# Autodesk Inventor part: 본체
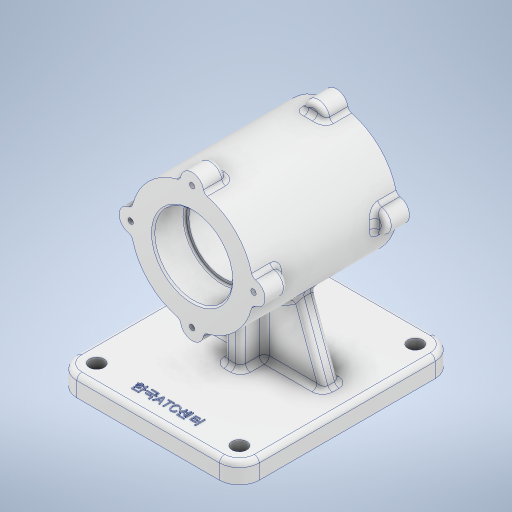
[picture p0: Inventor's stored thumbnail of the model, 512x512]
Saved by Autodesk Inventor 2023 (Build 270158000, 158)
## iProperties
Created: 2023-08
Part Number: 본체
Material: 알루미늄 6061
Document SubType Name: Modeling
Designer: asung
Density: 2.7 g/cm^3
Appearance: 알루미늄 - 평지
Author: asung
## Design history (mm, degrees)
sketch "스케치1"
  geometry: L1 (43, 65)-(-43, 65); L2 (-55, 53)-(-55, -53); L3 (-43, -65)-(43, -65); L4 (55, -53)-(55, 53); L5 (55, 65)-(-55, -65); L6 (-55, 65)-(55, -65); C1 r 4.5 at (-43, 53); C2 r 4.5 at (43, 53); C3 r 4.5 at (43, -53); C4 r 4.5 at (-43, -53); A1 r 12 centre (43, 53) between (55, 53) and (43, 65); A2 r 12 centre (-43, 53) between (-43, 65) and (-55, 53); A3 r 12 centre (-43, -53) between (-55, -53) and (-43, -65); A4 r 12 centre (43, -53) between (43, -65) and (55, -53); 1 further point
  constraints: 12 end point, 8 centre point, 8 point on circle, 8 point on line, 8 tangent, 4 coincident, 3 equal radius, 2 midpoint, 2 parallel, 1 horizontal, 1 perpendicular
  dimensions: "d0" = 110 distance of L6.end L5.end; "d1" = 130 distance of L5.end L6.start; "d2" = 12 radius of A1; "d3" = 9 diameter of C1; "d4" = 9 diameter of C2; "d5" = 9 diameter of C3; "d6" = 9 diameter of C4
extrude "돌출1" new body sketch "스케치1" distance "d7" = 12; taper "d8" = 0 deg
fillet "모깎기1" dims "d9" = 3
node "작업 평면1"
sketch "스케치2"
  geometry: L1 (-9, 12)-(115, 12) reference; L2 (118, 9)-(118, 0) reference; L3 (118, 0)-(-12, 0) reference; L4 (-12, 0)-(-12, 9) reference; A1 r 3 centre (-9, 9) between (-9, 12) and (-12, 9) reference; A2 r 3 centre (115, 9) between (118, 9) and (115, 12) reference; 1 further point
  node "절단 모서리 투영1"
sketch "스케치3"
  geometry: L1 (-9, 12)-(115, 12) reference; L2 (118, 9)-(118, 0) reference; L3 (118, 0)-(-12, 0) reference; L4 (-12, 0)-(-12, 9) reference; L5 (58, 0)-(58, 82); L6 (-12, 0)-(58, 0); L7 (14.5, 82)-(101.5, 82); L8 (101.5, 82)-(101.5, 119); L9 (101.5, 119)-(14.5, 119); L10 (14.5, 119)-(14.5, 82); A1 r 3 centre (-9, 9) between (-9, 12) and (-12, 9) reference; A2 r 3 centre (115, 9) between (118, 9) and (115, 12) reference; 1 further point
  constraints: 12 end point, 2 vertical, 1 horizontal, 1 midpoint, 1 perpendicular, 1 point on line
  dimensions: "d10" = 82 distance of L5.start L5.end; "d11" = 70 distance of L3.end L5.start; "d12" = 87 distance of L7.start L7.end; "d13" = 37 distance of L7.end L8.end; "d14" = 87 distance of L8.end L9.end
revolve "회전1" sketch "스케치3" stored, may be unused: angle "d15" = 90 deg
sketch "스케치4"
  geometry: C1 r 37 at (0, 0) reference; 2 further points
  constraints: 1 coincident
hole "구멍1" sketch "스케치4" at (0, 0) diameter "d16" = 42; stored, may be unused: countersink angle "d20" = 90 deg, drill point angle "d22" = 0 deg; dims "d17" = 10, "d18" = 47, "d19" = 19, "d21" = 45
sketch "스케치5"
  geometry: C1 r 37 at (0, 0) reference; 2 further points
  constraints: 1 coincident
hole "구멍2" sketch "스케치5" at (0, 0) diameter "d23" = 42; stored, may be unused: countersink angle "d27" = 90 deg, drill point angle "d29" = 0 deg; dims "d24" = 6, "d25" = 47, "d26" = 19, "d28" = 45
fillet "모깎기2" dims "d30" = 1
chamfer "모따기1" distance "d31" = 1; stored, may be unused: second distance "d32" = 2, angle "d33" = 45 deg
sketch "스케치6"
  geometry: C1 r 24.5 at (0, 0) reference; C2 r 7 at (0, 37); 2 further points
  constraints: 1 centre point, 1 vertical alignment, 1 other
  dimensions: "d34" = 14 diameter of C2
extrude "돌출2" join sketch "스케치6" distance "d35" = 14; taper "d36" = 0 deg
sketch "스케치7"
  geometry: 1 further point
sketch "스케치8"
  geometry: A1 r 7 centre (0, 0) between (6.969, -0.662) and (-6.969, -0.662) reference; 2 further points
  constraints: 1 coincident
hole "구멍3" sketch "스케치8" at (0, 0) diameter "d37" = 3.242; stored, may be unused: countersink angle "d41" = 90 deg, drill point angle "d43" = 118 deg; dims "d38" = 8, "d39" = 47, "d40" = 19, "d42" = 10
fillet "모깎기3" dims "d44" = 3
fillet "모깎기4" dims "d45" = 3
node "작업 평면2"
sketch "스케치9"
  geometry: L1 (0, -62)-(0, 62) reference; L2 (-43, -65)-(43, -65) reference; L3 (-55, 53)-(-55, -53) reference; L4 (43, 65)-(-43, 65) reference; L5 (55, -53)-(55, 53) reference; C1 r 4.5 at (43, 53) reference; C2 r 4.5 at (-43, 53) reference; C3 r 4.5 at (-43, -53) reference; C4 r 4.5 at (43, -53) reference; A1 r 12 centre (43, -53) between (43, -65) and (55, -53) reference; A2 r 12 centre (-43, -53) between (-55, -53) and (-43, -65) reference; A3 r 12 centre (-43, 53) between (-43, 65) and (-55, 53) reference; A4 r 12 centre (43, 53) between (55, 53) and (43, 65) reference; 2 further points
  constraints: 1 other
  dimensions: "d49" = 0 distance from line of L1 point (0, -53); "d50" = 0 vertical distance of C3.centre point (0, -53)
feature "엠보싱1" sketch "스케치9" dims "d0" = 110, "d1" = 130, "d2" = 12, "d3" = 9, "d4" = 9, "d5" = 9, "d6" = 9, "d51" = 0.5, "d52" = 0
sketch "스케치10"
  geometry: L1 (1.971, 12)-(1.971, 12.5) reference; L2 (1.971, 12.5)-(2.385, 12.5) reference; L3 (2.385, 12.5)-(2.385, 12) reference; L4 (2.385, 12)-(115, 12) reference; L5 (118, 9)-(118, 0) reference; L6 (118, 0)-(-12, 0) reference; L7 (-12, 0)-(-12, 9) reference; L8 (-9, 12)-(1.971, 12) reference; L9 (14.5, 57.5)-(15.5, 58.5) reference; L10 (15.5, 58.5)-(32.5, 58.5) reference; L11 (33.5, 59.5)-(33.5, 61) reference; L12 (33.5, 61)-(82.5, 61) reference; L13 (82.5, 61)-(82.5, 59.5) reference; L14 (83.5, 58.5)-(100.5, 58.5) reference; L15 (100.5, 58.5)-(101.5, 57.5) reference; L16 (101.5, 57.5)-(101.5, 46.621) reference; L17 (101.5, 46.621)-(91.5, 46.621) reference; L18 (91.5, 46.621)-(90.526, 45) reference; L19 (90.526, 45)-(91.5, 43.379) reference; L20 (91.5, 43.379)-(101.5, 43.379) reference; L21 (101.5, 43.379)-(101.5, 38) reference; L22 (101.5, 38)-(90.5, 38) reference; L23 (87.5, 41)-(87.5, 42) reference; L24 (84.5, 45)-(31.5, 45) reference; L25 (28.5, 42)-(28.5, 41) reference; L26 (25.5, 38)-(14.5, 38) reference; L27 (14.5, 38)-(14.5, 43.379) reference; L28 (14.5, 43.379)-(24.5, 43.379) reference; L29 (24.5, 43.379)-(25.474, 45) reference; L30 (25.474, 45)-(24.5, 46.621) reference; L31 (24.5, 46.621)-(14.5, 46.621) reference; L32 (14.5, 46.621)-(14.5, 57.5) reference; L33 (15.5, 105.5)-(14.5, 106.5) reference; L34 (14.5, 106.5)-(14.5, 117.379) reference; L35 (14.5, 117.379)-(24.5, 117.379) reference; L36 (24.5, 117.379)-(25.474, 119) reference; L37 (25.474, 119)-(24.5, 120.621) reference; L38 (24.5, 120.621)-(14.5, 120.621) reference; L39 (14.5, 120.621)-(14.5, 126) reference; L40 (14.5, 126)-(25.5, 126) reference; L41 (28.5, 123)-(28.5, 122) reference; L42 (31.5, 119)-(84.5, 119) reference; L43 (87.5, 122)-(87.5, 123) reference; L44 (90.5, 126)-(101.5, 126) reference; L45 (101.5, 126)-(101.5, 120.621) reference; L46 (101.5, 120.621)-(91.5, 120.621) reference; L47 (91.5, 120.621)-(90.526, 119) reference; L48 (90.526, 119)-(91.5, 117.379) reference; L49 (91.5, 117.379)-(101.5, 117.379) reference; L50 (101.5, 117.379)-(101.5, 106.5) reference; L51 (101.5, 106.5)-(100.5, 105.5) reference; L52 (100.5, 105.5)-(83.5, 105.5) reference; L53 (82.5, 104.5)-(82.5, 103) reference; L54 (82.5, 103)-(33.5, 103) reference; L55 (33.5, 103)-(33.5, 104.5) reference; L56 (32.5, 105.5)-(15.5, 105.5) reference; L57 (78.692, 12)-(78.692, 52.06); L58 (38.692, 12)-(38.692, 52.06); L59 (38.692, 52.06)-(78.692, 52.06); A1 r 3 centre (115, 9) between (118, 9) and (115, 12) reference; A2 r 3 centre (-9, 9) between (-9, 12) and (-12, 9) reference; A3 r 1 centre (32.5, 59.5) between (32.5, 58.5) and (33.5, 59.5) reference; A4 r 1 centre (83.5, 59.5) between (82.5, 59.5) and (83.5, 58.5) reference; A5 r 3 centre (90.5, 41) between (87.5, 41) and (90.5, 38) reference; A6 r 3 centre (84.5, 42) between (87.5, 42) and (84.5, 45) reference; A7 r 3 centre (31.5, 42) between (31.5, 45) and (28.5, 42) reference; A8 r 3 centre (25.5, 41) between (25.5, 38) and (28.5, 41) reference; A9 r 3 centre (25.5, 123) between (28.5, 123) and (25.5, 126) reference; A10 r 3 centre (31.5, 122) between (28.5, 122) and (31.5, 119) reference; A11 r 3 centre (84.5, 122) between (84.5, 119) and (87.5, 122) reference; A12 r 3 centre (90.5, 123) between (90.5, 126) and (87.5, 123) reference; A13 r 1 centre (83.5, 104.5) between (83.5, 105.5) and (82.5, 104.5) reference; A14 r 1 centre (32.5, 104.5) between (33.5, 104.5) and (32.5, 105.5) reference; 3 further points
  constraints: 6 end point, 1 horizontal
extrude "돌출3" join sketch "스케치10" stored distance "d55" = 10; taper "d56" = 0 deg
node "작업 평면3"
sketch "스케치11"
  geometry: L1 (5, -73.661)-(5, -107) reference; L2 (5, -107)-(52, -107) reference; L3 (55, -110)-(55, -119) reference; L4 (55, -119)-(-55, -119) reference; L5 (-55, -119)-(-55, -110) reference; L6 (-52, -107)-(-5, -107) reference; L7 (-5, -107)-(-5, -73.661) reference; L8 (-45.368, -119)-(-41, -119); L9 (-41, -110.525)-(-41, -107); L10 (45.368, -119)-(41, -119); L11 (41, -113)-(41, -107); L12 (-41, -107)-(-22.137, -55.175); L13 (41, -107)-(22.899, -57.267); L14 (-22.137, -55.175)-(-3.581, -66.905); L15 (-3.581, -66.905)-(11.041, -65.373); L16 (11.041, -65.373)-(23.165, -58); L17 (-41, -110.525)-(41, -113); C1 r 21 at (0, -37) reference; A1 r 3 centre (52, -110) between (55, -110) and (52, -107) reference; A2 r 3 centre (-52, -110) between (-52, -107) and (-55, -110) reference; A3 r 37 centre (0, -37) between (5, -73.661) and (-5, -73.661) reference; 1 further point
  constraints: 20 end point, 7 point on line, 2 perpendicular
  dimensions: "d57" = 14 distance of L4.end L8.end; "d58" = 14 distance of L3.end L10.end; "d59" = 110 deg angle of L13 L2; "d60" = 110 deg angle of L6 L12
extrude "돌출4" join sketch "스케치11" stored distance "d61" = 10; taper "d62" = 0 deg
fillet "모깎기5" dims "d63" = 3
fillet "모깎기6" dims "d64" = 3
feature "қ耀ҝ耀ҟ耀ҡ耀ң耀ҥ耀ҧ耀ҩ耀" dims "d0" = 110, "d1" = 130, "d2" = 12, "d3" = 9, "d4" = 9, "d5" = 9, "d6" = 9, "d7" = 12, "d8" = 0, "d9" = 3, "d10" = 82, "d11" = 70, "d12" = 87, "d13" = 37, "d14" = 87, "d15" = 90 deg, "d16" = 42, "d17" = 10, "d18" = 47, "d19" = 19, "d20" = 90 deg, "d21" = 45, "d22" = 0, "d23" = 42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
node "솔리드1"
pattern_circular "원형 패턴1" dims "d47" = 360 deg
mirror "미러1"
node "투영된 루프1"
node "투영된 루프2"
node "절단 모서리 투영2"
node "절단 모서리 투영3"
node "절단 모서리 투영4"
feature "A9D066F2-1C7D-4E18-AEED-F7BC21143FA4" dims "d16" = 42, "d17" = 10, "d18" = 47, "d19" = 19, "d20" = 90 deg, "d21" = 45, "d22" = 0
